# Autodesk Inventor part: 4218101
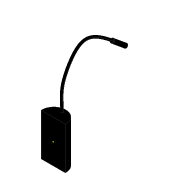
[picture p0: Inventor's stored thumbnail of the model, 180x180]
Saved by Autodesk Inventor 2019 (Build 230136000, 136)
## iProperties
Created: 2020-12
Part Number: 4218101
Material: Generic
Document SubType Name: Modeling
Designer: user
Density: 1 g/cm^3
Appearance: Default
Author: user
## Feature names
1. Extrusion1
2. Extrusion2
3. Sweep1
4. Extrusion3
5. Extrusion4
## Parameters: d6 = 0, d7 = 12 mm, d12 = 466 mm, d15 = 0, d16 = 0, d17 = 0, d18 = 15 mm, d19 = 75 mm, d20 = 0, d21 = 75 mm, d22 = 0
